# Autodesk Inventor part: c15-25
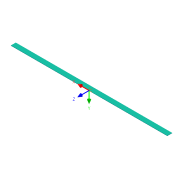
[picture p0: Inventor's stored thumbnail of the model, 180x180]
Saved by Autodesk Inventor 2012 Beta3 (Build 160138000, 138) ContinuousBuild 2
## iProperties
Created: 2011-02
Part Number: c15-25
Material: Default
Document SubType Name: Modeling
Designer: Beta-8540w
Density: 1 g/cm^3
Author: Beta-8540w
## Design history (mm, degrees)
sketch "Sketch1"
  geometry: L1 (-254, 7.938)-(254, 7.938); L2 (254, 7.938)-(254, -7.938); L3 (254, -7.938)-(-254, -7.938); L4 (-254, -7.938)-(-254, 7.938); 3 further points
  constraints: 8 end point, 2 midpoint, 2 parallel, 1 horizontal, 1 horizontal alignment, 1 perpendicular, 1 vertical alignment
  dimensions: "length" = 508 distance of L1.start L1.end; "d1" = 15.875 distance of L1.end L2.end
extrude "Extrusion1" new body sketch "Sketch1" taper "d3" = 0 deg; distance "thickness" = 1
body "Solid1"
other parameters: "d4" = 0, "d5" = 0, "d6" = 0, "d7" = 0, "d8" = 0, "d9" = 0
